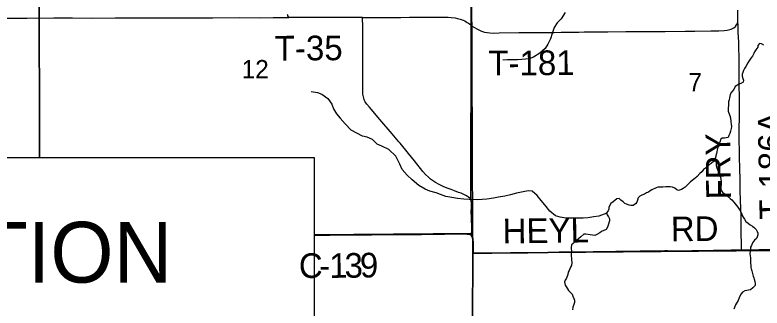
# Model space of a CAD drawing. Extents: x 0 to 34, y 0 to 22.
# Drawn here: x 4.726 to 6.446, y 19.142 to 19.817 of the extents above; entities that cross this region are included whole.
import ezdxf

# ---------------------------------------------------------------- set-up
doc = ezdxf.new("R2010")
doc.units = 0
for name, color, linetype in [('GM_X_County_Road', 7, 'Continuous'), ('GM_X_County_Road_Text', 7, 'Continuous'), ('GM_X_Minor_River', 7, 'Continuous'), ('GM_X_Section', 7, 'Continuous'), ('GM_X_Section_Text', 7, 'Continuous'), ('GM_X_Township_Road', 7, 'Continuous'), ('GM_X_Township_Road_Text', 7, 'Continuous'), ('SH_Text', 7, 'Continuous')]:
    doc.layers.add(name, color=color, linetype=linetype)

msp = doc.modelspace()

# ---------------------------------------------------------------- linework, layer by layer
at = {"layer": 'GM_X_County_Road'}
for points in [[(5.415, 19.3096), (5.4289, 19.3097), (5.4507, 19.31), (5.4693, 19.3103), (5.5035, 19.3106), (5.5469, 19.3109), (5.5935, 19.3111), (5.6619, 19.3117), (5.7147, 19.3123), (5.7582, 19.3126), (5.7674, 19.3124), (5.7704, 19.3121), (5.7732, 19.3113), (5.7759, 19.3096)], [(5.7759, 19.3096), (5.7776, 19.3078), (5.779, 19.3053), (5.7799, 19.3024), (5.7804, 19.2995), (5.7809, 19.2934), (5.7805, 19.2684)], [(6.3991, 19.2759), (6.4085, 19.2759), (6.4209, 19.2762), (6.4395, 19.2765), (6.4457, 19.2766), (6.4673, 19.2767), (6.4856, 19.2766), (6.5227, 19.277), (6.5724, 19.2772), (6.6003, 19.2775), (6.6345, 19.2778), (6.6532, 19.278), (6.6625, 19.278), (6.6904, 19.2783), (6.7153, 19.2786), (6.7463, 19.2787), (6.7711, 19.2787), (6.8478, 19.279)], [(5.7805, 19.2684), (5.793, 19.2682), (5.8054, 19.2681), (5.824, 19.2684), (5.8612, 19.2688), (5.8829, 19.2691), (5.907, 19.2694), (5.9348, 19.2697), (5.9524, 19.2703), (5.9698, 19.2709), (5.9785, 19.2712), (5.9886, 19.2715), (5.996, 19.2716), (6.0053, 19.2717), (6.0132, 19.2717), (6.0262, 19.2717), (6.0412, 19.2717), (6.057, 19.2719), (6.0711, 19.2721), (6.1005, 19.2724), (6.1091, 19.2726), (6.1149, 19.2728), (6.1209, 19.2729), (6.1338, 19.2731), (6.1453, 19.2732), (6.1652, 19.2735), (6.1798, 19.2737), (6.1956, 19.2739), (6.2125, 19.2741), (6.2222, 19.2742), (6.2285, 19.2743), (6.2409, 19.2741), (6.2534, 19.2741), (6.2845, 19.2744), (6.3093, 19.2747), (6.3342, 19.275), (6.3497, 19.2753), (6.3744, 19.2757), (6.3991, 19.2759)]]:
    msp.add_lwpolyline(points, dxfattribs=at)
at = {"layer": 'GM_X_Minor_River'}
for points in [[(5.9923, 19.8226), (5.9833, 19.8081), (5.9743, 19.7986), (5.9676, 19.7883), (5.9627, 19.7742), (5.9587, 19.762), (5.9527, 19.7499), (5.9463, 19.7396), (5.9347, 19.7292), (5.9196, 19.72), (5.9097, 19.7162), (5.8931, 19.7141), (5.8829, 19.7137), (5.8715, 19.7136), (5.8598, 19.7135), (5.8492, 19.7127)], [(6.4503, 19.7474), (6.4449, 19.7508), (6.4403, 19.7511), (6.4362, 19.7465), (6.4359, 19.7427), (6.4314, 19.7369), (6.4288, 19.732), (6.4269, 19.7281), (6.4236, 19.722), (6.4199, 19.7178), (6.4169, 19.7132), (6.4131, 19.7071), (6.4087, 19.6986), (6.4057, 19.694), (6.4031, 19.6891), (6.4013, 19.6849), (6.4002, 19.6807), (6.4002, 19.6757), (6.4014, 19.6704), (6.403, 19.6667), (6.4023, 19.6625), (6.3967, 19.659), (6.3925, 19.6574), (6.388, 19.6547), (6.3842, 19.6523), (6.3809, 19.6455), (6.3752, 19.6389), (6.3726, 19.6336), (6.3716, 19.6298), (6.3712, 19.626), (6.3701, 19.6214), (6.3687, 19.6168), (6.3683, 19.613), (6.3684, 19.6077), (6.3681, 19.6039), (6.3678, 19.5997), (6.3682, 19.5952), (6.3706, 19.5872), (6.3722, 19.5831), (6.373, 19.5781), (6.3738, 19.574), (6.3742, 19.5702), (6.3751, 19.5652), (6.3755, 19.5603), (6.3748, 19.5554), (6.3734, 19.5496), (6.3715, 19.5443), (6.3697, 19.5397), (6.3675, 19.5351), (6.3633, 19.5339), (6.3595, 19.5335), (6.3542, 19.533), (6.3504, 19.53), (6.3493, 19.5261), (6.3475, 19.5204), (6.3472, 19.5166), (6.3442, 19.5124), (6.3427, 19.5067), (6.3416, 19.5021), (6.3409, 19.4983), (6.3395, 19.4926), (6.3388, 19.4884), (6.3369, 19.4838), (6.334, 19.4796), (6.3287, 19.4746), (6.3245, 19.4719), (6.3196, 19.468)], [(5.408, 19.6406), (5.4224, 19.6384), (5.4327, 19.6343), (5.446, 19.6249), (5.4552, 19.6113), (5.4594, 19.6011), (5.4663, 19.589), (5.4747, 19.5792), (5.4861, 19.566)], [(6.0883, 19.3604), (6.0702, 19.3533), (6.0585, 19.3524), (6.0452, 19.3501), (6.0342, 19.3492), (6.0202, 19.3487), (6.0074, 19.3486), (5.9941, 19.3493), (5.9808, 19.3511), (5.9706, 19.3544), (5.9572, 19.3653), (5.9458, 19.3797), (5.9374, 19.3898), (5.9282, 19.4015), (5.9168, 19.4109), (5.9073, 19.412), (5.8808, 19.4065), (5.8672, 19.4026), (5.854, 19.3994), (5.8389, 19.3971), (5.8279, 19.3947), (5.812, 19.3927), (5.8018, 19.3918), (5.79, 19.3914), (5.7719, 19.392), (5.7594, 19.3927), (5.7446, 19.3941), (5.7321, 19.3966), (5.7177, 19.3992), (5.7055, 19.4036), (5.696, 19.407), (5.6812, 19.4114), (5.6702, 19.4159), (5.6557, 19.4241), (5.6401, 19.4369), (5.6291, 19.4478), (5.6172, 19.4614), (5.6122, 19.4731), (5.6026, 19.492), (5.587, 19.507), (5.571, 19.5145), (5.56, 19.5193), (5.549, 19.5299), (5.5368, 19.5355), (5.5258, 19.538), (5.5133, 19.5448), (5.5, 19.5519), (5.4861, 19.566)], [(6.3196, 19.468), (6.3155, 19.4642), (6.3114, 19.4607), (6.3073, 19.4557), (6.3027, 19.4518), (6.2967, 19.4453), (6.2915, 19.4407), (6.2851, 19.4356), (6.2806, 19.4322), (6.2727, 19.4241), (6.2689, 19.4202), (6.2644, 19.4171), (6.2602, 19.4152), (6.2534, 19.4124), (6.2496, 19.4139), (6.245, 19.4184), (6.2396, 19.4202), (6.2347, 19.4209), (6.2297, 19.4208), (6.224, 19.4212), (6.2176, 19.4207), (6.2138, 19.4206), (6.2062, 19.4202), (6.202, 19.4186), (6.1922, 19.4139), (6.1884, 19.4116), (6.1846, 19.4092), (6.1801, 19.4073), (6.1752, 19.4045), (6.1691, 19.4018), (6.1646, 19.3995), (6.1609, 19.3956), (6.1594, 19.3903), (6.1579, 19.3861), (6.1549, 19.3822), (6.1489, 19.3784), (6.144, 19.3783), (6.1398, 19.379), (6.134, 19.3812), (6.1298, 19.383), (6.126, 19.3864), (6.121, 19.3905), (6.1171, 19.3939), (6.1118, 19.3934), (6.1032, 19.3869), (6.0975, 19.3826), (6.0945, 19.3776), (6.0934, 19.3734), (6.0931, 19.3696), (6.0913, 19.3658), (6.0879, 19.3616), (6.0895, 19.3567), (6.0926, 19.3518), (6.0949, 19.3473), (6.0946, 19.3427), (6.0917, 19.3332), (6.0902, 19.3286), (6.0869, 19.3232), (6.0763, 19.3181), (6.0721, 19.3154), (6.0657, 19.3112), (6.0608, 19.3092), (6.0559, 19.3099), (6.0501, 19.3102), (6.0406, 19.312), (6.0353, 19.3119), (6.0289, 19.3061), (6.0236, 19.3011), (6.0154, 19.2953), (6.0108, 19.2907), (6.0071, 19.2872), (6.0064, 19.2804), (6.0069, 19.2712), (6.0066, 19.2671), (6.0067, 19.2617), (6.0071, 19.2568), (6.0075, 19.2523), (6.008, 19.2469), (6.0073, 19.2397), (6.0051, 19.2359), (6.0018, 19.2286), (5.9995, 19.2244), (5.9985, 19.2191), (5.9959, 19.2107), (5.9929, 19.2065), (5.9911, 19.2023), (5.9927, 19.1943), (5.9954, 19.1898), (6.0001, 19.1823), (6.0051, 19.1778), (6.0086, 19.1736), (6.0105, 19.1691), (6.0125, 19.1642), (6.0141, 19.1597), (6.0138, 19.1547), (6.0123, 19.1501), (6.0101, 19.1437), (6.0094, 19.1379)], [(6.336, 19.4825), (6.3393, 19.4804), (6.3405, 19.474), (6.3405, 19.4702), (6.3421, 19.4649), (6.3433, 19.4607), (6.3449, 19.457), (6.3461, 19.4532), (6.3488, 19.4475), (6.35, 19.4433), (6.3508, 19.4384), (6.3517, 19.4343), (6.3517, 19.4297), (6.3514, 19.4259), (6.3507, 19.4209), (6.3507, 19.4164), (6.3519, 19.4126), (6.3547, 19.4085), (6.3596, 19.4051), (6.3642, 19.4021), (6.3689, 19.3984), (6.3723, 19.3946), (6.3762, 19.3913), (6.3808, 19.386), (6.3843, 19.3823), (6.3874, 19.3781), (6.3901, 19.3744), (6.3963, 19.3653), (6.3983, 19.3604), (6.4002, 19.3551), (6.4026, 19.351), (6.4053, 19.3465), (6.4084, 19.3412), (6.4138, 19.3371), (6.4188, 19.3337), (6.4241, 19.3308), (6.4287, 19.3266), (6.4322, 19.3229), (6.4349, 19.3184), (6.4365, 19.3146), (6.4358, 19.3108), (6.4343, 19.3062), (6.4329, 19.302), (6.4287, 19.2981), (6.4239, 19.2924), (6.4213, 19.2859), (6.4194, 19.2821), (6.4191, 19.2783), (6.4184, 19.2726), (6.4181, 19.2672), (6.4185, 19.2623), (6.419, 19.2578), (6.4191, 19.2494), (6.4195, 19.2452), (6.42, 19.2403), (6.4204, 19.2357), (6.4208, 19.2319), (6.422, 19.2274), (6.424, 19.2217), (6.4256, 19.2157), (6.4272, 19.2119), (6.4276, 19.2081), (6.4292, 19.2028), (6.43, 19.1983), (6.4297, 19.1941), (6.4248, 19.1887), (6.4192, 19.1841), (6.415, 19.1829), (6.4105, 19.1824), (6.4059, 19.1816), (6.4006, 19.1785), (6.3976, 19.1747), (6.395, 19.1693), (6.3928, 19.1651), (6.391, 19.159), (6.3873, 19.1532), (6.3846, 19.149), (6.3824, 19.1429), (6.3806, 19.1391)]]:
    msp.add_lwpolyline(points, dxfattribs=at)
at = {"layer": 'GM_X_Section'}
for points in [[(4.783, 19.4891), (4.7808, 20.316), (3.7817, 20.3267), (3.7715, 19.4891)], [(5.415, 19.3104), (5.7798, 19.3134), (5.776, 20.2897), (5.7762, 20.3113), (4.7808, 20.316), (4.783, 19.4891), (5.415, 19.4891)], [(5.776, 20.2897), (6.8888, 20.2917), (6.9057, 19.2783), (5.7801, 19.2683), (5.7798, 19.3134)], [(4.7796, 18.772), (4.7762, 18.2959), (5.7756, 18.2855), (5.7801, 19.2683), (5.7798, 19.3134), (5.415, 19.3104), (5.415, 18.772)], [(5.7801, 19.2683), (6.9057, 19.2783), (6.9105, 18.2623), (5.7758, 18.2578), (5.7756, 18.2855)]]:
    msp.add_lwpolyline(points, close=True, dxfattribs=at)
at = {"layer": 'GM_X_Township_Road'}
for points in [[(5.7766, 19.8909), (5.7764, 19.7938), (5.7757, 19.3913), (5.7765, 19.3888), (5.777, 19.3824), (5.7768, 19.3731), (5.7766, 19.3645), (5.777, 19.3515), (5.7779, 19.3241), (5.778, 19.3206), (5.7778, 19.3178), (5.7774, 19.3153), (5.7764, 19.3122), (5.7757, 19.3101), (5.7774, 19.3084), (5.7788, 19.3058), (5.7797, 19.303), (5.7802, 19.3), (5.7807, 19.2939), (5.7803, 19.2689), (5.7801, 19.2592), (5.78, 19.2468), (5.78, 19.2282), (5.7799, 19.2096), (5.7798, 19.1972), (5.7797, 19.1816), (5.7796, 19.1599), (5.7796, 19.132)], [(5.7796, 19.132), (5.7796, 19.1599), (5.7797, 19.1816), (5.7798, 19.1972), (5.7799, 19.2096), (5.78, 19.2282), (5.78, 19.2468), (5.7801, 19.2592), (5.7803, 19.2689), (5.7807, 19.2939), (5.7802, 19.3), (5.7797, 19.303), (5.7788, 19.3058), (5.7774, 19.3084), (5.7757, 19.3101), (5.7764, 19.3122), (5.7774, 19.3153), (5.7778, 19.3178), (5.778, 19.3206), (5.7779, 19.3241), (5.777, 19.3515), (5.7766, 19.3645), (5.7768, 19.3731), (5.777, 19.3824), (5.7765, 19.3888), (5.7757, 19.3913), (5.7764, 19.7938), (5.7766, 19.8909)], [(5.3565, 19.8109), (5.3546, 19.8153), (5.354, 19.8169), (5.3532, 19.8184)], [(5.5261, 19.8114), (5.5319, 19.8115), (5.5502, 19.8113), (5.5685, 19.8111), (5.5967, 19.8115), (5.6143, 19.8116), (5.6344, 19.8117), (5.6383, 19.8117)], [(5.6383, 19.8117), (5.6706, 19.8121), (5.7131, 19.8119), (5.7231, 19.8118), (5.7301, 19.8116), (5.7392, 19.8105), (5.7449, 19.8093), (5.7509, 19.8075), (5.7553, 19.806), (5.7582, 19.8048), (5.7614, 19.8032), (5.7647, 19.8014), (5.7671, 19.7999), (5.77, 19.798), (5.7725, 19.7963), (5.7766, 19.7933)], [(6.3904, 19.8009), (6.3904, 19.8037), (6.3901, 19.8212), (6.3901, 19.828)], [(4.2806, 19.8102), (4.2848, 19.8102), (4.2916, 19.8102), (4.3182, 19.8101), (4.3614, 19.8101), (4.4, 19.8101), (4.4351, 19.8102), (4.4746, 19.8102), (4.5066, 19.81), (4.5778, 19.8103), (4.6194, 19.8102), (4.6735, 19.8097), (4.7077, 19.8097), (4.7546, 19.8097), (4.8159, 19.8101)], [(4.8159, 19.8101), (4.817, 19.8101), (4.8585, 19.8101), (4.9015, 19.8098), (4.9571, 19.8103), (5.0036, 19.8102), (5.0409, 19.8104), (5.0813, 19.8102), (5.1154, 19.8106), (5.1403, 19.8104), (5.1817, 19.8105), (5.2419, 19.811), (5.2891, 19.8108), (5.3205, 19.8109), (5.3565, 19.8109)], [(5.5261, 19.8114), (5.5073, 19.8112), (5.4852, 19.8111), (5.4417, 19.811), (5.4013, 19.8112), (5.3671, 19.8109), (5.3565, 19.8109)], [(5.6101, 19.525), (5.5948, 19.5434), (5.5664, 19.5764), (5.5419, 19.6045), (5.536, 19.6118), (5.5326, 19.6169), (5.5311, 19.6197), (5.5299, 19.6225), (5.5289, 19.6254), (5.5281, 19.6285), (5.5272, 19.6346), (5.5269, 19.6439), (5.527, 19.6843), (5.5271, 19.7247), (5.527, 19.7713), (5.5269, 19.7961), (5.5265, 19.8046), (5.5262, 19.8097), (5.5261, 19.8114)], [(5.7766, 19.7933), (5.7787, 19.7916), (5.7839, 19.7881), (5.7893, 19.7848), (5.7951, 19.7817), (5.8004, 19.7798), (5.8067, 19.7777), (5.8129, 19.7765), (5.8191, 19.7758), (5.8268, 19.7755), (5.8407, 19.7756), (5.8862, 19.7765), (5.9209, 19.7766), (5.949, 19.7768), (5.9671, 19.777), (5.9834, 19.7773), (6.0021, 19.7775), (6.0242, 19.7777), (6.0367, 19.778), (6.0481, 19.778), (6.091, 19.7783), (6.1326, 19.7787), (6.145, 19.779), (6.1593, 19.779), (6.1728, 19.7791), (6.1945, 19.7792), (6.2225, 19.7792), (6.2691, 19.7795), (6.2908, 19.7796), (6.328, 19.7802), (6.3466, 19.7805), (6.359, 19.7811), (6.3652, 19.7819), (6.3714, 19.7832), (6.3744, 19.7842), (6.3806, 19.7872), (6.3845, 19.7903), (6.3873, 19.794), (6.389, 19.7976), (6.3904, 19.8009)], [(6.3991, 19.2759), (6.3989, 19.2793), (6.3983, 19.2939), (6.3978, 19.3099), (6.3977, 19.3189), (6.3974, 19.331), (6.3977, 19.3551), (6.3972, 19.3687), (6.396, 19.3928), (6.3955, 19.4097), (6.3955, 19.4233), (6.3952, 19.4434), (6.3948, 19.4581), (6.3945, 19.469), (6.3939, 19.4839), (6.3937, 19.4986), (6.3936, 19.5091), (6.3935, 19.5236), (6.3934, 19.5328), (6.3933, 19.5388), (6.3933, 19.551), (6.3931, 19.5603), (6.3936, 19.5763), (6.3937, 19.589), (6.3937, 19.6042), (6.3936, 19.6318), (6.3934, 19.6504), (6.3933, 19.6617), (6.3933, 19.6708), (6.3933, 19.6805), (6.393, 19.6912), (6.393, 19.7047), (6.3928, 19.7186), (6.3924, 19.7432), (6.3921, 19.7535), (6.3914, 19.7667), (6.391, 19.777), (6.3907, 19.7871), (6.3905, 19.7937), (6.3904, 19.8009)], [(5.7759, 19.3908), (5.7742, 19.3932), (5.7731, 19.395), (5.7703, 19.3975), (5.7677, 19.3991), (5.7637, 19.4014), (5.7578, 19.4042), (5.7529, 19.4064), (5.7474, 19.4084), (5.738, 19.4117), (5.73, 19.4151), (5.721, 19.4184), (5.7122, 19.4219), (5.7027, 19.4265), (5.6943, 19.4309), (5.6876, 19.4354), (5.6827, 19.4391), (5.6779, 19.4431), (5.6713, 19.4496), (5.6652, 19.4566), (5.6459, 19.4809), (5.6322, 19.4978), (5.6127, 19.5219), (5.6101, 19.525)], [(5.7759, 19.3096), (5.7766, 19.3116), (5.7776, 19.3148), (5.778, 19.3172), (5.7782, 19.3201), (5.7781, 19.3236), (5.7772, 19.351), (5.7768, 19.364), (5.777, 19.3725), (5.7772, 19.3819), (5.7767, 19.3883), (5.7759, 19.3908)], [(5.7805, 19.2684), (5.7809, 19.2934), (5.7804, 19.2995), (5.7799, 19.3024), (5.779, 19.3053), (5.7776, 19.3078), (5.7759, 19.3096)], [(5.7792, 18.8145), (5.7791, 18.8738), (5.7792, 18.9141), (5.7793, 18.9638), (5.7793, 18.9979), (5.7791, 19.0259), (5.779, 19.0476), (5.7795, 19.088), (5.7798, 19.1314), (5.7798, 19.1594), (5.7799, 19.1811), (5.78, 19.1966), (5.7801, 19.209), (5.7802, 19.2276), (5.7802, 19.2463), (5.7803, 19.2587), (5.7805, 19.2684)]]:
    msp.add_lwpolyline(points, dxfattribs=at)
at = {"layer": 'SH_Text'}
msp.add_lwpolyline([(3.1951, 19.4891), (5.415, 19.4891), (5.415, 18.772), (3.1951, 18.772)], close=True, dxfattribs=at)

# ---------------------------------------------------------------- texts
at = {"layer": 'GM_X_County_Road_Text'}
for s, height, rotation, p in [('HEYL', 0.05682, 0.7677, (5.849, 19.2906)), ('RD', 0.05682, 0.4895, (6.2361, 19.2956)), ('C', 0.0568, 0.2849, (5.3798, 19.2111)), ('1', 0.0568, 0.3508, (5.4499, 19.2114)), ('3', 0.0568, 0.5394, (5.4851, 19.2116)), ('9', 0.0568, 1.2217, (5.5208, 19.212)), ('-', 0.0568, 0.2987, (5.4265, 19.2113))]:
    msp.add_text(s, height=height, rotation=rotation, dxfattribs=at).set_placement(p)
at = {"layer": 'GM_X_Section_Text'}
for s, height, p in [('12', 0.04186, (5.2481, 19.6714)), ('7', 0.0419, (6.2764, 19.6412))]:
    msp.add_text(s, height=height, rotation=0, dxfattribs=at).set_placement(p)
at = {"layer": 'GM_X_Township_Road_Text'}
for s, rotation, p in [('T-35', 0.3529, (5.3244, 19.712)), ('T-181', 0.2855, (5.8161, 19.6778)), ('T-186A', 91.0706, (6.4972, 19.3462)), ('FRY', 90.7074, (6.3743, 19.3925))]:
    msp.add_text(s, height=0.05682, rotation=rotation, dxfattribs=at).set_placement(p)
at = {"layer": 'SH_Text'}
msp.add_text('END ACQUISTION', height=0.14, dxfattribs=at).set_placement((3.4761, 19.2005))

doc.saveas('drawing.dxf')
